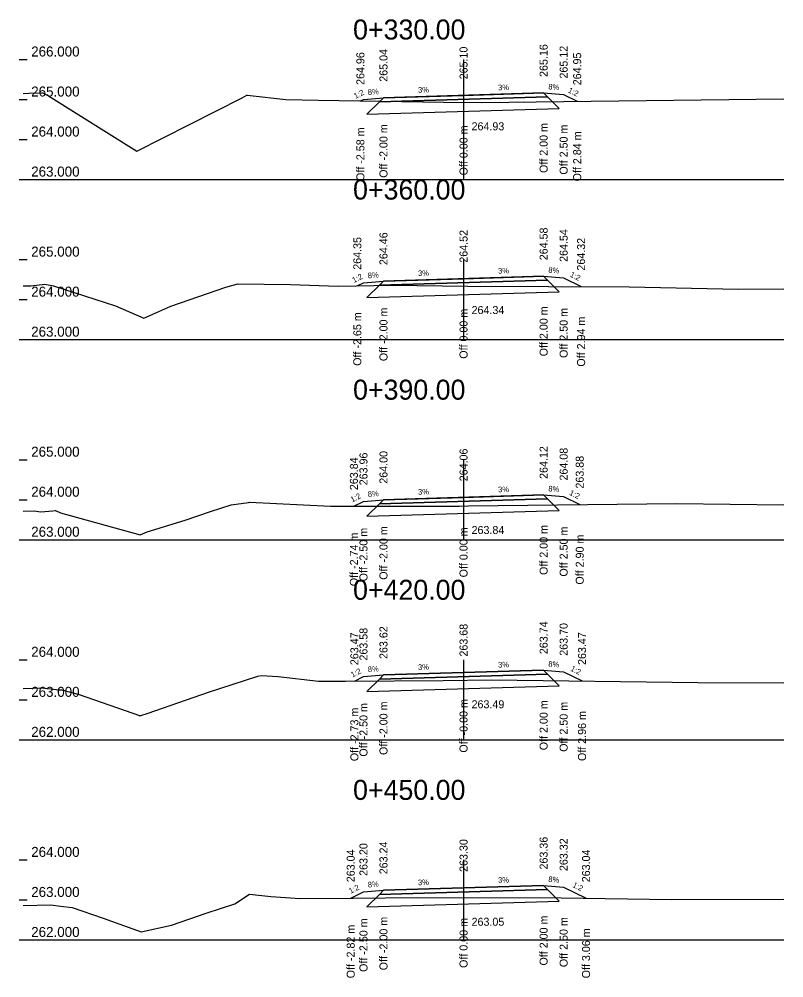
# Model space of a CAD drawing. Extents: x -550605 to -538780, y -1102367 to -1093705.
# Drawn here: x -541331.9 to -541312.8, y -1098198.5 to -1098174.55 of the extents above; entities that cross this region are included whole.
import ezdxf

# ---------------------------------------------------------------- set-up
doc = ezdxf.new("R2010")
doc.units = 0
for name, color, linetype in [('PŘ - offsety od osy', 7, 'Continuous'), ('PŘ - popis', 7, 'Continuous'), ('PŘ - příčné sklony', 7, 'Continuous'), ('PŘ - terén', 7, 'Continuous'), ('PŘ - vozovka', 7, 'Continuous'), ('PŘ - výšky offsetů', 7, 'Continuous')]:
    doc.layers.add(name, color=color, linetype=linetype)

msp = doc.modelspace()

# ---------------------------------------------------------------- linework, layer by layer
at = {"layer": 'PŘ - popis'}
for p, q in [((-541331.898, -1098175.553), (-541331.698, -1098175.553)), ((-541320.798, -1098175.553), (-541320.798, -1098178.553)), ((-541331.898, -1098176.553), (-541331.698, -1098176.553)), ((-541331.898, -1098177.553), (-541331.698, -1098177.553)), ((-541331.898, -1098178.553), (-541331.698, -1098178.553)), ((-541331.798, -1098178.553), (-541312.798, -1098178.553)), ((-541331.898, -1098180.553), (-541331.698, -1098180.553)), ((-541320.798, -1098180.553), (-541320.798, -1098182.553)), ((-541331.898, -1098181.553), (-541331.698, -1098181.553)), ((-541331.898, -1098182.553), (-541331.698, -1098182.553)), ((-541331.798, -1098182.553), (-541312.798, -1098182.553)), ((-541331.898, -1098185.553), (-541331.698, -1098185.553)), ((-541320.798, -1098185.553), (-541320.798, -1098187.553)), ((-541331.898, -1098186.553), (-541331.698, -1098186.553)), ((-541331.898, -1098187.553), (-541331.698, -1098187.553)), ((-541331.798, -1098187.553), (-541312.798, -1098187.553)), ((-541331.898, -1098190.553), (-541331.698, -1098190.553)), ((-541320.798, -1098190.553), (-541320.798, -1098192.553)), ((-541331.898, -1098191.553), (-541331.698, -1098191.553)), ((-541331.898, -1098192.553), (-541331.698, -1098192.553)), ((-541331.798, -1098192.553), (-541312.798, -1098192.553)), ((-541331.898, -1098195.553), (-541331.698, -1098195.553)), ((-541320.798, -1098195.553), (-541320.798, -1098197.553)), ((-541331.898, -1098196.553), (-541331.698, -1098196.553)), ((-541331.898, -1098197.553), (-541331.698, -1098197.553)), ((-541331.798, -1098197.553), (-541312.798, -1098197.553))]:
    msp.add_line(p, q, dxfattribs=at)
at = {"layer": 'PŘ - terén'}
for points in [[(-541331.798, -1098176.399), (-541331.653, -1098176.395), (-541331.335, -1098176.387), (-541331.335, -1098176.387), (-541331.304, -1098176.387), (-541331.167, -1098176.459), (-541328.957, -1098177.843), (-541328.956, -1098177.843), (-541326.332, -1098176.509), (-541326.213, -1098176.448), (-541326.191, -1098176.443), (-541326.191, -1098176.443), (-541326.13, -1098176.449), (-541325.239, -1098176.554), (-541324.433, -1098176.573), (-541321.303, -1098176.616), (-541320.362, -1098176.627), (-541320.361, -1098176.627), (-541320.361, -1098176.627), (-541312.798, -1098176.535)], [(-541331.798, -1098181.211), (-541331.605, -1098181.21), (-541331.259, -1098181.168), (-541331.042, -1098181.205), (-541329.491, -1098181.71), (-541328.783, -1098182.014), (-541328.11, -1098181.714), (-541328.109, -1098181.717), (-541326.74, -1098181.244), (-541326.44, -1098181.161), (-541325.12, -1098181.173), (-541323.932, -1098181.215), (-541323.931, -1098181.215), (-541322.586, -1098181.193), (-541320.692, -1098181.214), (-541316.66, -1098181.234), (-541313.929, -1098181.289), (-541312.798, -1098181.286)], [(-541331.798, -1098186.84), (-541331.522, -1098186.833), (-541331.356, -1098186.852), (-541331.055, -1098186.831), (-541330.996, -1098186.824), (-541330.993, -1098186.825), (-541330.868, -1098186.878), (-541328.874, -1098187.431), (-541328.702, -1098187.354), (-541328.699, -1098187.355), (-541327.751, -1098187.066), (-541327.119, -1098186.846), (-541326.601, -1098186.677), (-541326.171, -1098186.619), (-541326.145, -1098186.61), (-541324.121, -1098186.712), (-541323.872, -1098186.713), (-541320.906, -1098186.713), (-541320.673, -1098186.708), (-541320.672, -1098186.709), (-541315.48, -1098186.643), (-541312.798, -1098186.682)], [(-541331.798, -1098191.267), (-541331.316, -1098191.256), (-541330.91, -1098191.303), (-541330.845, -1098191.299), (-541330.843, -1098191.299), (-541330.399, -1098191.421), (-541328.889, -1098191.948), (-541328.889, -1098191.949), (-541328.886, -1098191.951), (-541328.679, -1098191.887), (-541327.171, -1098191.364), (-541325.937, -1098190.96), (-541325.847, -1098190.948), (-541325.427, -1098190.967), (-541325.426, -1098190.967), (-541324.419, -1098191.088), (-541323.75, -1098191.088), (-541321.308, -1098191.07), (-541321.306, -1098191.07), (-541320.097, -1098191.055), (-541314.944, -1098191.117), (-541312.798, -1098191.128)], [(-541331.798, -1098196.694), (-541331.111, -1098196.678), (-541330.87, -1098196.706), (-541330.577, -1098196.738), (-541330.576, -1098196.738), (-541330.575, -1098196.738), (-541329.804, -1098197.006), (-541328.851, -1098197.35), (-541328.85, -1098197.351), (-541328.849, -1098197.352), (-541328.097, -1098197.184), (-541327.224, -1098196.881), (-541326.512, -1098196.648), (-541326.141, -1098196.408), (-541325.615, -1098196.47), (-541325.613, -1098196.47), (-541324.881, -1098196.521), (-541323.559, -1098196.511), (-541321.952, -1098196.495), (-541318.363, -1098196.504), (-541315.6, -1098196.538), (-541312.798, -1098196.533)]]:
    msp.add_lwpolyline(points, dxfattribs=at)
at = {"layer": 'PŘ - vozovka'}
for points in [[(-541323.375, -1098176.588), (-541323.298, -1098176.549), (-541322.798, -1098176.509), (-541320.798, -1098176.449), (-541318.798, -1098176.389), (-541318.298, -1098176.429), (-541317.96, -1098176.598)], [(-541323.452, -1098181.207), (-541323.298, -1098181.13), (-541322.798, -1098181.09), (-541320.798, -1098181.03), (-541318.798, -1098180.97), (-541318.298, -1098181.01), (-541317.862, -1098181.228)], [(-541323.537, -1098186.713), (-541323.298, -1098186.593), (-541322.798, -1098186.553), (-541320.798, -1098186.493), (-541318.798, -1098186.433), (-541318.298, -1098186.473), (-541317.896, -1098186.674)], [(-541323.525, -1098191.086), (-541323.298, -1098190.972), (-541322.798, -1098190.932), (-541320.798, -1098190.872), (-541318.798, -1098190.812), (-541318.298, -1098190.852), (-541317.839, -1098191.082)], [(-541323.617, -1098196.511), (-541323.298, -1098196.352), (-541322.798, -1098196.312), (-541320.798, -1098196.252), (-541318.798, -1098196.192), (-541318.298, -1098196.232), (-541317.738, -1098196.512)]]:
    msp.add_lwpolyline(points, dxfattribs=at)
for points in [[(-541322.898, -1098176.612), (-541323.211, -1098176.922), (-541318.409, -1098176.778), (-541318.698, -1098176.486)], [(-541322.798, -1098176.509), (-541322.898, -1098176.612), (-541318.698, -1098176.486), (-541318.798, -1098176.389)], [(-541322.898, -1098181.193), (-541323.211, -1098181.503), (-541318.409, -1098181.359), (-541318.698, -1098181.067)], [(-541322.798, -1098181.09), (-541322.898, -1098181.193), (-541318.698, -1098181.067), (-541318.798, -1098180.97)], [(-541322.898, -1098186.656), (-541323.211, -1098186.966), (-541318.409, -1098186.821), (-541318.698, -1098186.53)], [(-541322.798, -1098186.553), (-541322.898, -1098186.656), (-541318.698, -1098186.53), (-541318.798, -1098186.433)], [(-541322.798, -1098190.932), (-541322.898, -1098191.035), (-541318.698, -1098190.909), (-541318.798, -1098190.812)], [(-541322.898, -1098191.035), (-541323.211, -1098191.345), (-541318.409, -1098191.201), (-541318.698, -1098190.909)], [(-541322.898, -1098196.415), (-541323.211, -1098196.725), (-541318.409, -1098196.581), (-541318.698, -1098196.289)], [(-541322.798, -1098196.312), (-541322.898, -1098196.415), (-541318.698, -1098196.289), (-541318.798, -1098196.192)]]:
    msp.add_lwpolyline(points, close=True, dxfattribs=at)

# ---------------------------------------------------------------- texts
at = {"layer": 'PŘ - offsety od osy'}
for s, p in [('Off -2.00 m', (-541322.698, -1098178.509)), ('Off 0.00 m', (-541320.698, -1098178.449)), ('Off 2.00 m', (-541318.698, -1098178.389)), ('Off 2.50 m', (-541318.198, -1098178.429)), ('Off -2.58 m', (-541323.275, -1098178.588)), ('Off 2.84 m', (-541317.86, -1098178.598)), ('Off -2.00 m', (-541322.698, -1098183.09)), ('Off 2.00 m', (-541318.698, -1098182.97)), ('Off 2.50 m', (-541318.198, -1098183.01)), ('Off -2.65 m', (-541323.352, -1098183.207)), ('Off 0.00 m', (-541320.698, -1098183.03)), ('Off 2.94 m', (-541317.762, -1098183.228)), ('Off -2.50 m', (-541323.198, -1098188.593)), ('Off -2.00 m', (-541322.698, -1098188.553)), ('Off 0.00 m', (-541320.698, -1098188.493)), ('Off 2.00 m', (-541318.698, -1098188.433)), ('Off 2.50 m', (-541318.198, -1098188.473)), ('Off -2.74 m', (-541323.437, -1098188.713)), ('Off 2.90 m', (-541317.796, -1098188.674)), ('Off -0.00 m', (-541320.698, -1098192.872)), ('Off 2.00 m', (-541318.698, -1098192.812)), ('Off -2.73 m', (-541323.425, -1098193.086)), ('Off -2.50 m', (-541323.198, -1098192.972)), ('Off -2.00 m', (-541322.698, -1098192.932)), ('Off 2.50 m', (-541318.198, -1098192.852)), ('Off 2.96 m', (-541317.739, -1098193.082)), ('Off -2.50 m', (-541323.198, -1098198.352)), ('Off -2.00 m', (-541322.698, -1098198.312)), ('Off 0.00 m', (-541320.698, -1098198.252)), ('Off 2.00 m', (-541318.698, -1098198.192)), ('Off 2.50 m', (-541318.198, -1098198.232)), ('Off -2.82 m', (-541323.517, -1098198.511)), ('Off 3.06 m', (-541317.638, -1098198.512))]:
    msp.add_text(s, height=0.2, rotation=90, dxfattribs=at).set_placement(p)
at = {"layer": 'PŘ - popis'}
for s, height, p in [('0+330.00', 0.5, (-541323.558, -1098175.053)), ('266.000', 0.25, (-541331.598, -1098175.478)), ('265.000', 0.25, (-541331.598, -1098176.478)), ('264.000', 0.25, (-541331.598, -1098177.478)), ('263.000', 0.25, (-541331.598, -1098178.478)), ('0+360.00', 0.5, (-541323.558, -1098179.053)), ('265.000', 0.25, (-541331.598, -1098180.478)), ('264.000', 0.25, (-541331.598, -1098181.478)), ('263.000', 0.25, (-541331.598, -1098182.478)), ('0+390.00', 0.5, (-541323.558, -1098184.053)), ('265.000', 0.25, (-541331.598, -1098185.478)), ('264.000', 0.25, (-541331.598, -1098186.478)), ('263.000', 0.25, (-541331.598, -1098187.478)), ('0+420.00', 0.5, (-541323.558, -1098189.053)), ('264.000', 0.25, (-541331.598, -1098190.478)), ('263.000', 0.25, (-541331.598, -1098191.478)), ('262.000', 0.25, (-541331.598, -1098192.478)), ('0+450.00', 0.5, (-541323.558, -1098194.053)), ('264.000', 0.25, (-541331.598, -1098195.478)), ('263.000', 0.25, (-541331.598, -1098196.478)), ('262.000', 0.25, (-541331.598, -1098197.478))]:
    msp.add_text(s, height=height, dxfattribs=at).set_placement(p)
at = {"layer": 'PŘ - příčné sklony'}
for s, rotation, p in [('3%', 1.7184, (-541321.933, -1098176.383)), ('3%', 1.7184, (-541319.933, -1098176.323)), ('8%', 355.4261, (-541318.683, -1098176.298)), ('1:2', 333.4349, (-541318.201, -1098176.366)), ('1:2', 26.5651, (-541323.498, -1098176.538)), ('8%', 4.5739, (-541323.183, -1098176.44)), ('3%', 1.7184, (-541321.933, -1098180.964)), ('3%', 1.7184, (-541319.933, -1098180.904)), ('8%', 355.4261, (-541318.683, -1098180.879)), ('1:2', 26.5651, (-541323.537, -1098181.138)), ('8%', 4.5739, (-541323.183, -1098181.021)), ('1:2', 333.4349, (-541318.152, -1098180.971)), ('8%', 4.5739, (-541323.183, -1098186.484)), ('3%', 1.7184, (-541321.933, -1098186.427)), ('3%', 1.7184, (-541319.933, -1098186.367)), ('8%', 355.4261, (-541318.683, -1098186.342)), ('1:2', 333.4349, (-541318.169, -1098186.425)), ('1:2', 26.5651, (-541323.579, -1098186.622)), ('3%', 1.7184, (-541319.933, -1098190.747)), ('8%', 355.4261, (-541318.683, -1098190.722)), ('1:2', 26.5651, (-541323.573, -1098190.998)), ('8%', 4.5739, (-541323.183, -1098190.863)), ('3%', 1.7184, (-541321.933, -1098190.807)), ('1:2', 333.4349, (-541318.141, -1098190.819)), ('8%', 4.5739, (-541323.183, -1098196.243)), ('3%', 1.7184, (-541321.933, -1098196.186)), ('3%', 1.7184, (-541319.933, -1098196.126)), ('8%', 355.4261, (-541318.683, -1098196.101)), ('1:2', 333.4349, (-541318.09, -1098196.224)), ('1:2', 26.5651, (-541323.619, -1098196.401))]:
    msp.add_text(s, height=0.14, rotation=rotation, dxfattribs=at).set_placement(p)
at = {"layer": 'PŘ - výšky offsetů'}
for s, p in [('265.04', (-541322.698, -1098176.109)), ('265.10', (-541320.698, -1098176.049)), ('265.16', (-541318.698, -1098175.989)), ('265.12', (-541318.198, -1098176.029)), ('264.96', (-541323.275, -1098176.188)), ('264.95', (-541317.86, -1098176.198)), ('264.52', (-541320.698, -1098180.63)), ('264.58', (-541318.698, -1098180.57)), ('264.54', (-541318.198, -1098180.61)), ('264.35', (-541323.352, -1098180.807)), ('264.46', (-541322.698, -1098180.69)), ('264.32', (-541317.762, -1098180.828)), ('264.00', (-541322.698, -1098186.153)), ('264.06', (-541320.698, -1098186.093)), ('264.12', (-541318.698, -1098186.033)), ('264.08', (-541318.198, -1098186.073)), ('263.84', (-541323.437, -1098186.313)), ('263.96', (-541323.198, -1098186.193)), ('263.88', (-541317.796, -1098186.274)), ('263.68', (-541320.698, -1098190.472)), ('263.74', (-541318.698, -1098190.412)), ('263.70', (-541318.198, -1098190.452)), ('263.47', (-541323.425, -1098190.686)), ('263.58', (-541323.198, -1098190.572)), ('263.62', (-541322.698, -1098190.532)), ('263.47', (-541317.739, -1098190.682)), ('263.20', (-541323.198, -1098195.952)), ('263.24', (-541322.698, -1098195.912)), ('263.30', (-541320.698, -1098195.852)), ('263.36', (-541318.698, -1098195.792)), ('263.32', (-541318.198, -1098195.832)), ('263.04', (-541323.517, -1098196.111)), ('263.04', (-541317.638, -1098196.112))]:
    msp.add_text(s, height=0.2, rotation=90, dxfattribs=at).set_placement(p)
for s, p in [('264.93', (-541320.598, -1098177.322)), ('264.34', (-541320.598, -1098181.913)), ('263.84', (-541320.598, -1098187.41)), ('263.49', (-541320.598, -1098191.764)), ('263.05', (-541320.598, -1098197.198))]:
    msp.add_text(s, height=0.2, dxfattribs=at).set_placement(p)

doc.saveas('drawing.dxf')
